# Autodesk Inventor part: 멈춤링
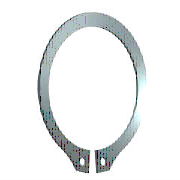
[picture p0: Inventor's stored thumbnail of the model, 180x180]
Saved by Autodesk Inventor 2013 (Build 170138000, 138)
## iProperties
Company: 한국ATC센터
IsCustomPart: 1
Created: 2014-10
Part Number: 멈춤링
Material: 강, 연강
Description: 리테이닝 링(C형)
Document SubType Name: Modeling
Standard: KS B 1336
Designer: 한국ATC센터
Standards Organization: KS
Language: ko-KR
Size Designation: 25 x 1.2
Categories: <MemberInstance><Categories><Category DisplayName="샤프트 부품" InternalName="7f7aeb1f-a693-4053-b835-cee3144e0d98" Mnemonic="SHFT"><Category DisplayName="써클립" Inter
Density: 7.86 g/cm^3
Mass: 2.3429 g
Surface Area: 7.2498 cm^2
Volume: 0.298079 cm^3
Author: KYOUNG IL JANG
Revision Number: 1
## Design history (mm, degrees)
sketch "스케치1"
  geometry: L1 (-6, 0)-(6, 0) reference; L2 (0, 20.189)-(0, -80.536) reference; L3 (-48.09, 0)-(48.09, 0) reference; L4 (-0.5, -24.44)-(-0.5, -28.74); L5 (-0.5, -6.54)-(-0.5, -13.29); L6 (-2.795, 3.1)-(3.672, 3.1); L7 (0.5, -6.54)-(0.5, -13.29); L8 (0.5, -24.44)-(0.5, -28.74); C1 r 1 at (-2, -26.606); C2 r 1 at (2, -26.606); A1 r 11.95 centre (0, -12.5) between (0.5, -24.44) and (-0.5, -24.44); A2 r 14.825 centre (0, -11.725) between (5.202, -25.608) and (-5.202, -25.608); A3 r 16.247 centre (0, -12.5) between (-2.281, -28.586) and (-0.5, -28.74); A4 r 2 centre (-2, -26.606) between (-3.952, -27.043) and (-2.281, -28.586); A5 r 2 centre (-5.903, -27.48) between (-3.952, -27.043) and (-5.202, -25.608); A6 r 2 centre (5.903, -27.48) between (5.202, -25.608) and (3.952, -27.043); A7 r 2 centre (2, -26.606) between (2.281, -28.586) and (3.952, -27.043); A8 r 16.247 centre (0, -12.5) between (0.5, -28.74) and (2.281, -28.586)
  constraints: 16 point on circle, 12 end point, 10 centre point, 9 symmetric about line, 5 point on line, 4 tangent, 3 coincident, 2 horizontal, 1 perpendicular, 1 vertical, 5 other
  dimensions: "d0" = 23.9 diameter of A1 (= ND); "d1" = 4.3 distance of L4.end L4.start (= SRB2); "d6" = 0.5 distance between parallel lines of L2 L5 (= 0.25 x SD5); "d7" = 3.1 distance between parallel lines of L6 L3 (= SRB1); "d8" = 0.775 distance of A1.centre A2.centre (= 0.25 x SRB1); "d9" = 2 radius of A4 (= SD5); "d10" = 2 radius of A5 (= SD5); "d11" = 1.5 distance from line of L4 A4.centre (= 0.75 x SD5); "d12" = 2 diameter of C1 (= SD5); "d13" = 2 diameter of C2 (= SD5); "d14" = 12.5 distance from line of A1.centre L1 (= 0.5 x WD)
extrude "본체" new body sketch "스케치1" distance "d2" = 1.2 (= SD); taper "d3" = 0 deg
workaxis "Work Axis1"
workplane "Work Plane1"
body "Solid1"
other parameters: "WD" = 25 (= WDMIN) [user parameter; used in 1 equation term], "SD" = 1.2 [user parameter; used in 1 equation term], "SRB1" = 3.1 [user parameter; used in 2 equation terms], "ND" = 23.9 [user parameter; used in 1 equation term], "SRB2" = 4.3 [user parameter; used in 1 equation term], "SD5" = 2 [user parameter; used in 6 equation terms], "d15" = 0, "d16" = 0, "d17" = 0, "d41" = 0, "d42" = 0, "WDMIN" = 25 [user parameter; used in 1 equation term], "SD3" = 23.2 [user parameter], "WDMAX" = 26 [user parameter]
